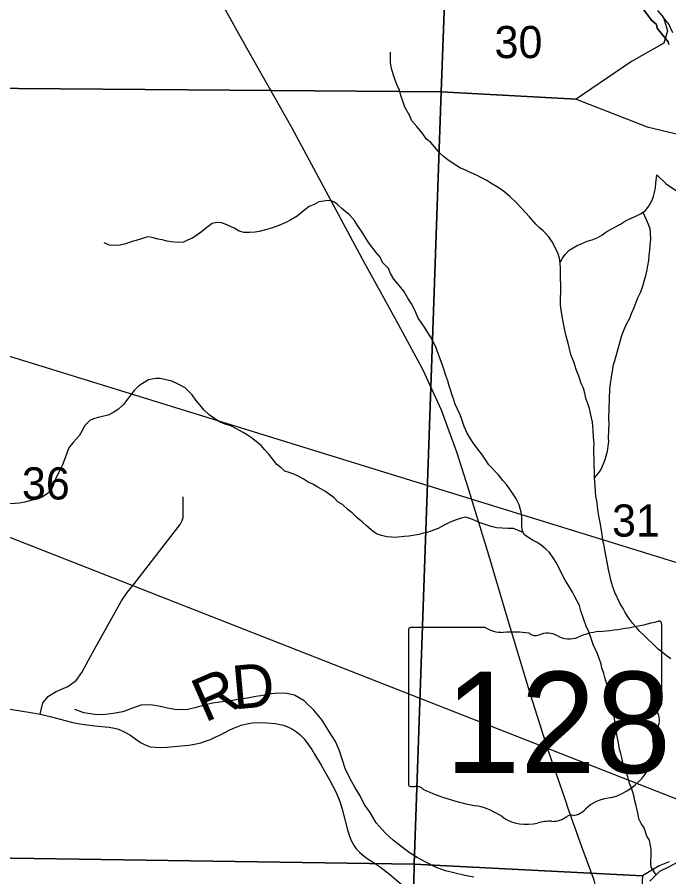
# Model space of a CAD drawing. Extents: x -7.5 to 26.5, y 3.5 to 25.5.
# Drawn here: x 0.131 to 0.979, y 19.097 to 20.216 of the extents above; entities that cross this region are included whole.
import ezdxf

# ---------------------------------------------------------------- set-up
doc = ezdxf.new("R2010")
doc.units = 0
for name, color, linetype in [('GM_X_Corporation', 7, 'Continuous'), ('GM_X_County_Road', 7, 'Continuous'), ('GM_X_County_Road_Text', 7, 'Continuous'), ('GM_X_Major_River', 7, 'Continuous'), ('GM_X_Minor_River', 7, 'Continuous'), ('GM_X_Section_Text', 7, 'Continuous'), ('GM_X_State_Location', 7, 'Continuous'), ('GM_X_State_Route', 7, 'Continuous'), ('GM_X_State_Shield', 7, 'Continuous'), ('GM_X_Township_Road', 7, 'Continuous'), ('SH_Text', 7, 'Continuous')]:
    doc.layers.add(name, color=color, linetype=linetype)

msp = doc.modelspace()

# ---------------------------------------------------------------- linework, layer by layer
at = {"layer": 'GM_X_Corporation'}
for points in [[(0.6899, 20.3049), (0.6831, 20.1191), (-0.3082, 20.1265)], [(0.9645, 20.2247), (0.9722, 20.2155), (0.9775, 20.1983), (0.9725, 20.1821), (0.9307, 20.1585), (0.8586, 20.1095), (0.6831, 20.1191), (0.6899, 20.3049)], [(0.9453, 20.2273), (0.9567, 20.2122), (0.9631, 20.2064), (0.9641, 20.2018), (0.9781, 20.184), (0.9792, 20.1805)], [(0.9792, 20.1805), (0.9781, 20.184), (0.9641, 20.2018), (0.9631, 20.2064), (0.9567, 20.2122), (0.9453, 20.2273)], [(0.9796, 19.1166), (0.9666, 19.1113), (0.9447, 19.0982), (0.6477, 19.1133), (0.6831, 20.1191), (0.8586, 20.1095), (0.951, 20.0735), (1.0274, 20.055)], [(0.6301, 18.1235), (0.6477, 19.1133), (0.9447, 19.0982), (0.944, 19.0834)]]:
    msp.add_lwpolyline(points, dxfattribs=at)
for points in [[(-0.3082, 20.1265), (0.6831, 20.1191), (0.6477, 19.1133), (-0.3419, 19.1283)], [(0.6477, 19.1133), (0.6301, 18.1235), (-0.3746, 18.1372), (-0.3419, 19.1283)]]:
    msp.add_lwpolyline(points, close=True, dxfattribs=at)
at = {"layer": 'GM_X_County_Road'}
msp.add_lwpolyline([(0.1219, 19.3151), (0.1354, 19.3131), (0.1515, 19.3105), (0.1613, 19.3086), (0.1741, 19.3055), (0.1937, 19.3004), (0.2037, 19.2978), (0.2124, 19.2961), (0.2221, 19.2947), (0.2323, 19.2937), (0.2457, 19.2923), (0.251, 19.2918), (0.2577, 19.2906), (0.263, 19.289), (0.2706, 19.2858), (0.2779, 19.2817), (0.2919, 19.2719), (0.2959, 19.2696), (0.2998, 19.2678), (0.3043, 19.2663), (0.3106, 19.2656), (0.3194, 19.2655), (0.3265, 19.2659), (0.3397, 19.2669), (0.3544, 19.2683), (0.3619, 19.2695), (0.37, 19.2714), (0.3764, 19.2735), (0.3827, 19.2758), (0.3889, 19.2786), (0.3966, 19.2821), (0.408, 19.2882), (0.4141, 19.2911), (0.4226, 19.2943), (0.43, 19.2961), (0.4372, 19.2972), (0.4454, 19.2978), (0.4559, 19.2976), (0.4669, 19.2965), (0.4777, 19.2942), (0.4851, 19.2914), (0.4896, 19.2891), (0.4949, 19.2856), (0.4994, 19.2818), (0.5046, 19.2766), (0.5105, 19.2686), (0.5145, 19.2627), (0.5183, 19.2566), (0.5269, 19.2422), (0.5376, 19.2232), (0.5461, 19.2068), (0.5511, 19.195), (0.5542, 19.1852), (0.5612, 19.158), (0.5636, 19.1497), (0.5663, 19.1434), (0.5696, 19.1372), (0.5724, 19.1333), (0.5765, 19.129), (0.5831, 19.1232), (0.588, 19.1198), (0.5947, 19.1157), (0.6041, 19.1093), (0.6157, 19.1004), (0.6384, 19.0812)], dxfattribs=at)
at = {"layer": 'GM_X_Major_River'}
for points in [[(0.9714, 20.2162), (0.979, 20.2065), (0.984, 20.1961)], [(0.991, 19.1159), (0.9787, 19.1095), (0.9671, 19.1038), (0.9545, 19.0912)]]:
    msp.add_lwpolyline(points, dxfattribs=at)
at = {"layer": 'GM_X_Minor_River'}
for points in [[(0.6859, 20.0346), (0.6811, 20.0389), (0.6746, 20.0468), (0.6695, 20.053), (0.6639, 20.0574), (0.6592, 20.0644), (0.6512, 20.0738), (0.6446, 20.0812), (0.6422, 20.0878), (0.6358, 20.099), (0.6337, 20.1055), (0.6306, 20.114), (0.6285, 20.1213), (0.6261, 20.1263), (0.6229, 20.134), (0.6212, 20.1394), (0.6192, 20.1463), (0.6178, 20.1517), (0.6172, 20.1567), (0.6171, 20.1624), (0.617, 20.1704), (0.617, 20.1706)], [(0.9818, 19.3806), (0.9759, 19.385), (0.9704, 19.3893), (0.9652, 19.3933), (0.9579, 19.4008), (0.9523, 19.4059), (0.9461, 19.4118), (0.9413, 19.4162), (0.9369, 19.4213), (0.9322, 19.4268), (0.9271, 19.4338), (0.9224, 19.4412), (0.9196, 19.4462), (0.9153, 19.4532), (0.9089, 19.4671), (0.9065, 19.4744), (0.9038, 19.4832), (0.9025, 19.4897), (0.9008, 19.497), (0.8989, 19.5066), (0.8979, 19.5115), (0.8963, 19.52), (0.8951, 19.528), (0.8934, 19.5353), (0.8925, 19.5425), (0.8903, 19.5559), (0.8887, 19.5643), (0.8878, 19.5693), (0.8868, 19.5746), (0.8862, 19.5796), (0.8853, 19.5865), (0.8844, 19.5926), (0.8838, 19.5987), (0.8833, 19.6059), (0.8828, 19.6113), (0.8825, 19.6162), (0.8824, 19.6238), (0.882, 19.6333), (0.8819, 19.6413), (0.8817, 19.6478), (0.8816, 19.6554), (0.8818, 19.6611), (0.8813, 19.6695), (0.8809, 19.6786), (0.8797, 19.6889), (0.8784, 19.6943), (0.8758, 19.7065), (0.8741, 19.7115), (0.8713, 19.72), (0.87, 19.7265), (0.868, 19.733), (0.8652, 19.7392), (0.8621, 19.7488), (0.8586, 19.7576), (0.8558, 19.7661), (0.8516, 19.7769), (0.85, 19.7842), (0.848, 19.7918), (0.8457, 19.801), (0.8433, 19.8106), (0.842, 19.8171), (0.8405, 19.8267), (0.8392, 19.8351), (0.8383, 19.8412), (0.8382, 19.8496), (0.8385, 19.8587), (0.8385, 19.8685), (0.8383, 19.875), (0.8382, 19.8826), (0.8384, 19.8891), (0.8379, 19.8959), (0.837, 19.9024), (0.8346, 19.9093), (0.8317, 19.9148), (0.8279, 19.9233), (0.8224, 19.9307), (0.8155, 19.9381), (0.8107, 19.9417), (0.8059, 19.9468), (0.7979, 19.9562), (0.7869, 19.968), (0.7799, 19.9751), (0.7729, 19.9822), (0.7656, 19.9881), (0.7596, 19.9925), (0.7548, 19.9957), (0.7474, 20.0002), (0.7422, 20.0034), (0.7362, 20.0066), (0.7287, 20.0103), (0.719, 20.0148), (0.7138, 20.0173), (0.7082, 20.0197), (0.7033, 20.0226), (0.6985, 20.0258), (0.6918, 20.0302), (0.6859, 20.0346)], [(0.9622, 20), (0.9636, 20.0108), (0.9758, 19.999), (0.9904, 19.9891), (1.0054, 19.9819), (1.0191, 19.9723), (1.032, 19.9594), (1.0435, 19.9492), (1.0534, 19.9368), (1.064, 19.9235), (1.0759, 19.9129), (1.082, 19.9021), (1.0896, 19.8886)], [(0.8376, 19.8985), (0.838, 19.8974), (0.8408, 19.9023), (0.8444, 19.9071), (0.8495, 19.9126), (0.8549, 19.9159), (0.86, 19.9187), (0.865, 19.9212), (0.8731, 19.9244), (0.8792, 19.9264), (0.8858, 19.9289), (0.892, 19.9324), (0.8974, 19.9364), (0.904, 19.94), (0.909, 19.9429), (0.9164, 19.9468), (0.9226, 19.9508), (0.9303, 19.9543), (0.9361, 19.9571), (0.943, 19.9607), (0.9489, 19.9643), (0.9532, 19.9702), (0.9577, 19.9777), (0.9594, 19.9826), (0.9607, 19.9878), (0.9617, 19.9939), (0.9622, 20)], [(0.6762, 19.7867), (0.6691, 19.7999), (0.6611, 19.8124), (0.6572, 19.8182), (0.6532, 19.8244), (0.65, 19.8317), (0.6447, 19.8426), (0.6397, 19.8503), (0.6343, 19.8593), (0.6267, 19.869), (0.6215, 19.8749), (0.6172, 19.8823), (0.6144, 19.8888), (0.6067, 19.8967), (0.6036, 19.9037), (0.5985, 19.9099), (0.5941, 19.9154), (0.5883, 19.9228), (0.5851, 19.9286), (0.5793, 19.9376), (0.5739, 19.945), (0.5703, 19.9512), (0.5637, 19.9586), (0.5589, 19.9626), (0.5537, 19.9669), (0.5482, 19.9721), (0.5434, 19.9757), (0.5381, 19.9774), (0.5328, 19.9772), (0.5237, 19.9756), (0.5175, 19.9724), (0.5113, 19.9695), (0.5035, 19.9637), (0.4957, 19.9572), (0.4872, 19.9521), (0.4806, 19.9486), (0.4717, 19.9447), (0.4636, 19.9419), (0.4544, 19.9392), (0.446, 19.9372), (0.4407, 19.9363), (0.4334, 19.9358), (0.4262, 19.9356), (0.4202, 19.9374), (0.4135, 19.9414), (0.4042, 19.9459), (0.3971, 19.9484), (0.3906, 19.9486), (0.3849, 19.9473), (0.3782, 19.9422), (0.3712, 19.9368), (0.3595, 19.9284), (0.3538, 19.9264), (0.3476, 19.9231), (0.3407, 19.9226), (0.3317, 19.9237), (0.3264, 19.9246), (0.32, 19.9264), (0.3143, 19.9273), (0.3068, 19.9291), (0.3011, 19.9301), (0.2954, 19.9284), (0.2861, 19.9253), (0.2808, 19.9239), (0.2727, 19.9208), (0.267, 19.9195), (0.262, 19.9189), (0.251, 19.9193), (0.2443, 19.9222)], [(0.9452, 19.9621), (0.9496, 19.9529), (0.9524, 19.9467), (0.9545, 19.9409), (0.9547, 19.9352), (0.9552, 19.9268), (0.9545, 19.9196), (0.9539, 19.9128), (0.9533, 19.9064), (0.9527, 19.8992), (0.9513, 19.8924), (0.9503, 19.8856), (0.949, 19.8792), (0.9468, 19.872), (0.9447, 19.8656), (0.9418, 19.8574), (0.9389, 19.851), (0.9364, 19.8446), (0.9335, 19.8375), (0.9302, 19.8297), (0.9281, 19.824), (0.924, 19.817), (0.922, 19.8121), (0.9195, 19.8061), (0.9174, 19.8012), (0.9122, 19.7824), (0.91, 19.7749), (0.9065, 19.7613), (0.9056, 19.7553), (0.9046, 19.7504), (0.9037, 19.7443), (0.9027, 19.739), (0.9021, 19.7318), (0.9008, 19.6935), (0.9009, 19.687), (0.9003, 19.6684), (0.9005, 19.6635), (0.8999, 19.6574), (0.8989, 19.6506), (0.8972, 19.6446), (0.8959, 19.6397), (0.8934, 19.6333), (0.8905, 19.6273), (0.8869, 19.6218), (0.8825, 19.6168)], [(0.9628, 19.0995), (0.9561, 19.1094), (0.9559, 19.1143), (0.9564, 19.1265), (0.9562, 19.1322), (0.9552, 19.1375), (0.9539, 19.1448), (0.9507, 19.1498), (0.9469, 19.1606), (0.9433, 19.1664), (0.9401, 19.1726), (0.9392, 19.178), (0.9378, 19.1837), (0.9365, 19.1899), (0.9348, 19.1956), (0.9339, 19.201), (0.9322, 19.2071), (0.9301, 19.2136), (0.928, 19.2186), (0.9257, 19.2271), (0.9233, 19.2348), (0.9212, 19.2409), (0.9195, 19.2459), (0.9182, 19.2524), (0.9165, 19.2574), (0.9151, 19.2632), (0.9135, 19.2712), (0.9119, 19.2796), (0.9104, 19.2899), (0.9098, 19.2953), (0.9076, 19.3079), (0.907, 19.3129), (0.9057, 19.3201), (0.9027, 19.3309), (0.8997, 19.3428), (0.8987, 19.3477), (0.896, 19.3566), (0.8946, 19.3615), (0.8922, 19.3689), (0.8912, 19.3738), (0.8881, 19.3823), (0.8864, 19.3873), (0.8807, 19.3993), (0.8787, 19.4058), (0.8749, 19.4158), (0.8717, 19.4231), (0.8686, 19.432), (0.8648, 19.4431), (0.8628, 19.4501), (0.8567, 19.4613), (0.8539, 19.4675), (0.8488, 19.476), (0.8441, 19.483), (0.8417, 19.488), (0.836, 19.4996), (0.8324, 19.5062), (0.8285, 19.5124), (0.8238, 19.519), (0.819, 19.5234), (0.8127, 19.5293), (0.8071, 19.5325), (0.8019, 19.5354), (0.7971, 19.5382), (0.7915, 19.5422), (0.7883, 19.5476), (0.7878, 19.5545), (0.788, 19.5602), (0.7878, 19.5655), (0.7872, 19.5716), (0.7845, 19.5812), (0.7803, 19.5901), (0.7723, 19.6018), (0.768, 19.6076), (0.7632, 19.6131), (0.7574, 19.6201), (0.7449, 19.6335), (0.741, 19.6393), (0.7366, 19.6459), (0.7308, 19.6537), (0.7247, 19.6619), (0.7196, 19.6693), (0.7167, 19.6744), (0.7129, 19.6833), (0.7094, 19.6936), (0.7077, 19.6986), (0.7042, 19.7056), (0.7013, 19.7122), (0.6989, 19.7191), (0.6972, 19.7241), (0.6955, 19.7298), (0.6934, 19.736), (0.6914, 19.7425), (0.689, 19.7498), (0.6859, 19.759), (0.6835, 19.7664), (0.6817, 19.7714), (0.6779, 19.7817), (0.6762, 19.7867)], [(0.7898, 19.545), (0.777, 19.5503), (0.7698, 19.5502), (0.7622, 19.5508), (0.755, 19.5514), (0.7478, 19.5528), (0.74, 19.5554), (0.7336, 19.5579), (0.7269, 19.5608), (0.7216, 19.5632), (0.7152, 19.565), (0.7091, 19.564), (0.7026, 19.5616), (0.6945, 19.5585), (0.6868, 19.5546), (0.679, 19.5503), (0.6729, 19.5482), (0.6648, 19.5454), (0.6599, 19.5445), (0.6537, 19.5424), (0.6407, 19.5406), (0.6354, 19.54), (0.6232, 19.5389), (0.6183, 19.5391), (0.6122, 19.5397), (0.6051, 19.5414), (0.5987, 19.5435), (0.5924, 19.5483), (0.5854, 19.5543), (0.5806, 19.5586), (0.5736, 19.5645), (0.567, 19.5709), (0.5618, 19.5748), (0.5545, 19.5816), (0.5489, 19.5848), (0.5437, 19.5903), (0.5323, 19.5987), (0.5226, 19.6043), (0.5159, 19.608), (0.5099, 19.6108), (0.5032, 19.6149), (0.4961, 19.6189), (0.4913, 19.621), (0.4853, 19.6231), (0.4797, 19.6252), (0.4749, 19.6292), (0.4693, 19.6339), (0.4631, 19.6417), (0.4588, 19.6472), (0.4533, 19.6527), (0.4489, 19.6586), (0.436, 19.6685), (0.4308, 19.6717), (0.4252, 19.6753), (0.4159, 19.6806), (0.4092, 19.6839), (0.402, 19.6864), (0.3964, 19.6885), (0.3897, 19.6925), (0.3812, 19.6985), (0.3742, 19.7048), (0.3687, 19.7115), (0.3636, 19.7174), (0.3589, 19.7244), (0.3498, 19.7334), (0.3408, 19.7383), (0.3326, 19.7424), (0.3228, 19.7446), (0.3175, 19.7456), (0.3115, 19.7458), (0.3023, 19.7438), (0.2941, 19.7392), (0.2891, 19.7359), (0.2836, 19.73), (0.2776, 19.7222), (0.2733, 19.7171), (0.2701, 19.7122), (0.263, 19.7056), (0.2572, 19.7017), (0.2498, 19.6981), (0.2422, 19.6961), (0.2368, 19.6948), (0.2307, 19.6931), (0.2257, 19.691), (0.2194, 19.6844), (0.2153, 19.6773), (0.2117, 19.6709), (0.2042, 19.6625), (0.1994, 19.6569), (0.1969, 19.6509), (0.1949, 19.6457), (0.1903, 19.6333), (0.1858, 19.6247), (0.1805, 19.6139), (0.1779, 19.6064), (0.1759, 19.6015), (0.1707, 19.596), (0.1637, 19.5913), (0.1572, 19.5888), (0.1507, 19.5872), (0.1411, 19.5848)], [(0.1411, 19.5848), (0.1342, 19.5835), (0.1221, 19.5825)], [(0.7253, 19.0965), (0.7139, 19.0988), (0.6992, 19.1022), (0.6887, 19.1048), (0.6755, 19.1097), (0.6628, 19.1162), (0.6519, 19.1222), (0.6419, 19.1282), (0.6211, 19.144), (0.6103, 19.1538), (0.5982, 19.1671), (0.5906, 19.1806), (0.5829, 19.1914), (0.5775, 19.2022), (0.5707, 19.2138), (0.5645, 19.2247), (0.5581, 19.2378), (0.5549, 19.2477), (0.5508, 19.2608), (0.5454, 19.2731), (0.5378, 19.2851), (0.528, 19.301), (0.5173, 19.3138), (0.5048, 19.3259), (0.4921, 19.3335), (0.4815, 19.3357), (0.4713, 19.336), (0.4618, 19.3352), (0.4514, 19.3332), (0.4419, 19.3319), (0.4308, 19.3296), (0.4186, 19.3276), (0.406, 19.3257), (0.395, 19.3245), (0.3854, 19.3229), (0.3747, 19.3205), (0.364, 19.3174), (0.3533, 19.3147), (0.3389, 19.3143), (0.3268, 19.3166), (0.3154, 19.3192), (0.3049, 19.321), (0.2923, 19.3206), (0.2812, 19.3167), (0.2685, 19.3118), (0.2563, 19.3095), (0.243, 19.308), (0.2323, 19.3083), (0.218, 19.3106), (0.2063, 19.3147)]]:
    msp.add_lwpolyline(points, dxfattribs=at)
at = {"layer": 'GM_X_State_Route'}
for points in [[(0.5968, 19.872), (0.5838, 19.8956), (0.4889, 20.0716), (0.4301, 20.1759), (0.3986, 20.2327), (0.3896, 20.2492), (0.366, 20.2973), (0.3375, 20.3583), (0.2705, 20.5707), (0.2027, 20.7838), (0.1701, 20.8958), (0.1663, 20.9449), (0.1735, 20.9929), (0.1881, 21.0328), (0.2176, 21.0781), (0.2213, 21.0822), (0.2613, 21.1268), (0.3579, 21.223)], [(0.8441, 19.1979), (0.8223, 19.2619), (0.799, 19.3345), (0.7686, 19.4348), (0.7451, 19.5159), (0.7188, 19.6007), (0.7034, 19.6498), (0.6835, 19.7046), (0.659, 19.7574), (0.6275, 19.8162), (0.5968, 19.872)], [(0.8995, 19.0064), (0.8987, 19.0256), (0.8912, 19.0563), (0.8818, 19.0924), (0.8675, 19.1314), (0.8486, 19.1847), (0.8441, 19.1979)]]:
    msp.add_lwpolyline(points, dxfattribs=at)
at = {"layer": 'GM_X_State_Shield'}
for p, q in [((0.6403, 19.4181), (0.6403, 19.218)), ((0.74, 19.4215), (0.6435, 19.4215)), ((0.9699, 19.3218), (0.9699, 19.4265)), ((0.9698, 19.3218), (0.9699, 19.3218))]:
    msp.add_line(p, q, dxfattribs=at)
for centre, major_axis, start_param, end_param in [((0.8524, 19.6944), (0.3495, 0), 4.814394, 5.042369), ((0.9662, 19.4269), (0.00367, 0), 6.141152, 7.989035), ((0.644, 19.4185), (0.00382, 0), 1.712693, 3.28349), ((0.763, 19.4448), (0.037, 0), 4.042523, 4.731795), ((0.7753, 19.3092), (0.133, 0), 1.404758, 1.657858), ((0.8055, 19.4196), (0.0107, 0), 3.836095, 5.185415), ((0.8212, 19.3964), (0.0222, 0), 0.950623, 2.079405), ((0.8498, 19.4282), (0.0267, 0), 4.081561, 5.145723), ((0.897, 19.3604), (0.0703, 0), 1.699011, 2.107814), ((0.969, 19.3141), (0.00568, 0), 1.883978, 3.671073), ((0.9659, 19.3214), (0.00393, 0), 5.05454, 6.418171), ((0.9329, 19.3009), (0.0341, 0), 5.934695, 6.695948), ((0.983, 19.278), (0.0248, 0), 2.387724, 3.262537), ((0.872, 19.2647), (0.0874, 0), 5.101752, 6.440018), ((0.6441, 19.2175), (0.00385, 0), 3.00124, 4.508301), ((0.6447, 19.238), (0.0294, 0), 4.665946, 4.897461), ((0.6507, 19.2064), (0.0106, 0), 0.519207, 1.627899), ((0.7845, 19.3862), (0.2524, 0), 4.195997, 4.488961), ((0.9089, 19.1618), (0.0479, 0), 1.647645, 2.488434), ((0.7093, 19.1281), (0.079, 0), 0.823519, 1.323587), ((0.8482, 19.1986), (0.0282, 0), 4.937069, 5.64225), ((0.7947, 19.2054), (0.0501, 0), 4.026481, 4.996735), ((0.8273, 19.1905), (0.0267, 0), 4.691044, 5.507374), ((0.8514, 19.1711), (0.00752, 0), 1.147584, 2.315152), ((0.8236, 19.1363), (0.0412, 0), 1.495662, 1.94098)]:
    msp.add_ellipse(centre, major_axis=major_axis, ratio=0.8, start_param=start_param, end_param=end_param, dxfattribs=at)
at = {"layer": 'GM_X_Township_Road'}
msp.add_lwpolyline([(0.1613, 19.3086), (0.1648, 19.3234), (0.1718, 19.3322), (0.182, 19.3382), (0.197, 19.3449), (0.208, 19.3524), (0.2154, 19.363), (0.2298, 19.3893), (0.267, 19.4561), (0.2742, 19.4671), (0.2838, 19.4786), (0.3343, 19.5438), (0.3431, 19.5554), (0.3459, 19.5609), (0.3473, 19.5649), (0.3474, 19.5719), (0.3472, 19.5916)], dxfattribs=at)
at = {"layer": 'SH_Text'}
msp.add_lwpolyline([(2.5135, 19.0346), (-2.7067, 20.6498), (2.5135, 18.5999)], close=True, dxfattribs=at)

# ---------------------------------------------------------------- texts
at = {"layer": 'GM_X_County_Road_Text'}
for s, rotation, p in [('D', 5.114, (0.4134, 19.3148)), ('R', 23.6332, (0.3753, 19.2973))]:
    msp.add_text(s, height=0.0568, rotation=rotation, dxfattribs=at).set_placement(p)
at = {"layer": 'GM_X_Section_Text'}
for s, p in [('30', (0.7524, 20.1628)), ('36', (0.1374, 19.5882)), ('31', (0.9053, 19.5399))]:
    msp.add_text(s, height=0.04186, rotation=0, dxfattribs=at).set_placement(p)
at = {"layer": 'GM_X_State_Location'}
for s, p in [('s', (0.8014, 19.3047)), ('r', (0.8013, 19.3047))]:
    msp.add_text(s, height=0.000189, dxfattribs=at).set_placement(p)
msp.add_text('128', height=0.000189, rotation=0, dxfattribs=at).set_placement((0.7345, 19.291))
at = {"layer": 'GM_X_State_Shield'}
msp.add_text('128', height=0.13184, dxfattribs=at).set_placement((0.6879, 19.2321))

doc.saveas('drawing.dxf')
